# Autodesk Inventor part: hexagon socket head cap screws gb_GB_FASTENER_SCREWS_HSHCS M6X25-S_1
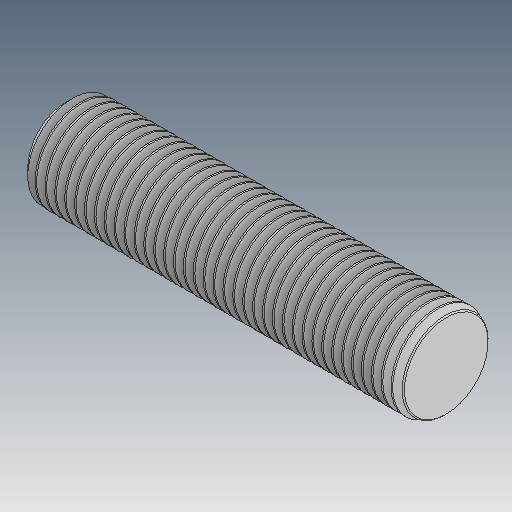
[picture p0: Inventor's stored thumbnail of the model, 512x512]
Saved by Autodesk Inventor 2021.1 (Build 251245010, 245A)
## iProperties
Created: 2019-04
Part Number: hexagon socket head cap screws gb_GB_FASTENER_SCREWS_HSHCS M6X25-S_1
Material: Ogólny
Document SubType Name: Modeling
Designer: user
Density: 1 g/cm^3
Appearance: Domyślna
Author: user
Revision Number: ÈÎºÎ
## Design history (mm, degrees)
feature "ÊäÈë1"
node "Bryła1"
